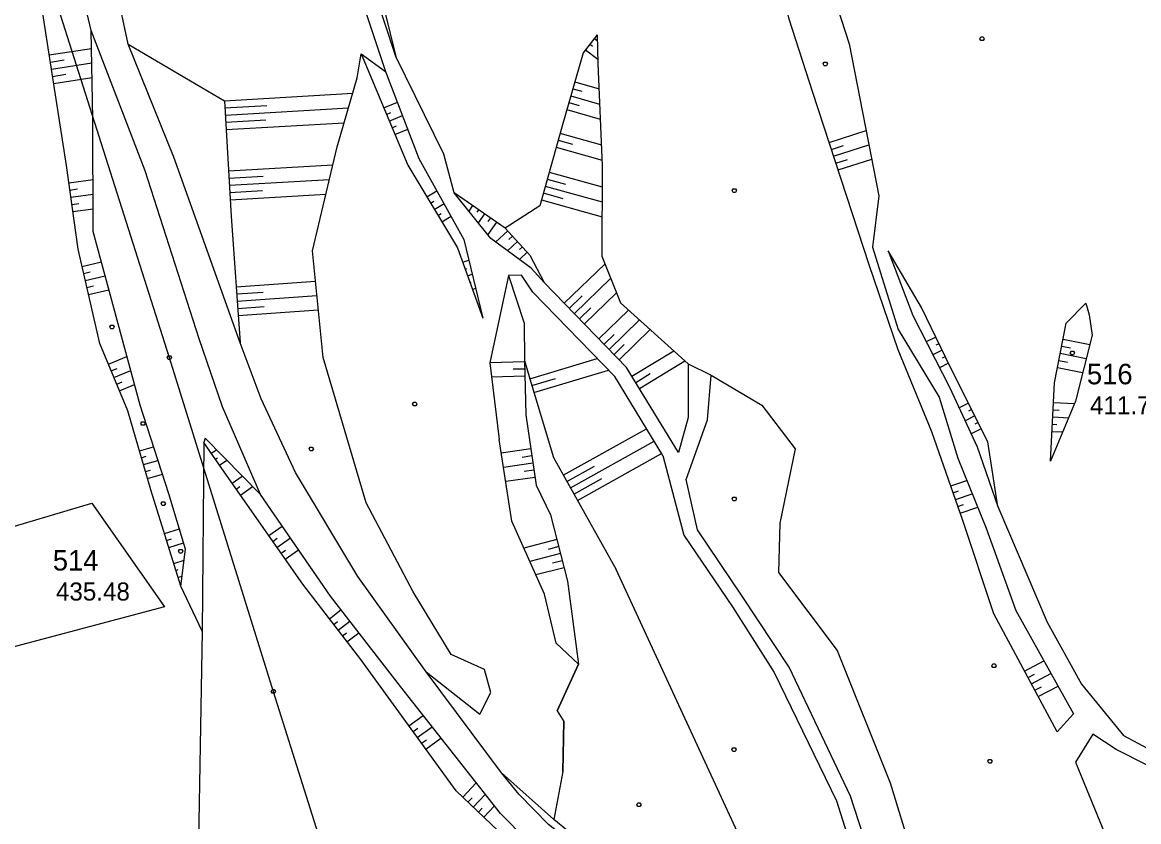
# Model space of a CAD drawing. Extents: x -664960 to -662754, y -993849 to -991145.
# Drawn here: x -663833.4 to -663648.1, y -993552.6 to -993419.9 of the extents above; entities that cross this region are included whole.
import ezdxf

# ---------------------------------------------------------------- set-up
doc = ezdxf.new("R2010")
doc.units = 0
for name, color, linetype in [('Vrstva 1', 7, 'Continuous'), ('Vrstva 13', 7, 'Continuous'), ('Vrstva 23', 7, 'Continuous'), ('Vrstva 27', 7, 'Continuous'), ('Vrstva 37', 7, 'Continuous'), ('Vrstva 57', 7, 'Continuous'), ('Vrstva 63', 7, 'Continuous'), ('Vrstva 8', 7, 'Continuous')]:
    doc.layers.add(name, color=color, linetype=linetype)

msp = doc.modelspace()

# ---------------------------------------------------------------- linework, layer by layer
at = {"layer": 'Vrstva 13'}
for points in [[(-663673.965, -993422.37), (-663673.786, -993422.67), (-663673.965, -993422.97), (-663674.326, -993422.97), (-663674.506, -993422.67), (-663674.326, -993422.37), (-663673.965, -993422.37)], [(-663699.967, -993426.545), (-663699.787, -993426.845), (-663699.967, -993427.145), (-663700.327, -993427.145), (-663700.507, -993426.845), (-663700.327, -993426.545), (-663699.967, -993426.545)], [(-663715.06, -993447.588), (-663714.88, -993447.888), (-663715.06, -993448.188), (-663715.42, -993448.188), (-663715.6, -993447.888), (-663715.42, -993447.588), (-663715.06, -993447.588)], [(-663768.107, -993483.011), (-663767.927, -993483.311), (-663768.107, -993483.611), (-663768.467, -993483.611), (-663768.647, -993483.311), (-663768.467, -993483.011), (-663768.107, -993483.011)], [(-663785.301, -993490.467), (-663785.121, -993490.767), (-663785.301, -993491.067), (-663785.661, -993491.067), (-663785.841, -993490.767), (-663785.661, -993490.467), (-663785.301, -993490.467)], [(-663715.062, -993498.751), (-663714.883, -993499.051), (-663715.062, -993499.351), (-663715.423, -993499.351), (-663715.602, -993499.051), (-663715.423, -993498.751), (-663715.062, -993498.751)], [(-663715.121, -993540.383), (-663714.941, -993540.683), (-663715.121, -993540.983), (-663715.481, -993540.983), (-663715.661, -993540.683), (-663715.481, -993540.383), (-663715.121, -993540.383)], [(-663730.907, -993549.527), (-663730.727, -993549.827), (-663730.907, -993550.127), (-663731.267, -993550.127), (-663731.447, -993549.827), (-663731.267, -993549.527), (-663730.907, -993549.527)]]:
    msp.add_lwpolyline(points, dxfattribs=at)
at = {"layer": 'Vrstva 23'}
for points in [[(-663661.79, -993680.84), (-663666.37, -993671.83), (-663676.16, -993653.43), (-663682.14, -993639.66), (-663688.35, -993624.08), (-663695.39, -993604.45), (-663700.87, -993593.48), (-663716.11, -993576), (-663718.69, -993573.73), (-663734.89, -993562.06), (-663746.09, -993553.11), (-663750.94, -993548.15), (-663753.89, -993544.52), (-663766.4, -993527.77), (-663777.73, -993511.96), (-663788.08, -993494.69), (-663793.77, -993482.43), (-663797.29, -993473.16), (-663808.27, -993442.31), (-663815.88, -993423.57), (-663819.75, -993405.36)], [(-663667.19, -993679.26), (-663670.59, -993672.44), (-663678.35, -993658.11), (-663686.67, -993641.66), (-663696.49, -993616.58), (-663704.03, -993599.55), (-663711.55, -993587), (-663718.59, -993580.09), (-663723.96, -993575.78), (-663738.28, -993566.28), (-663745.54, -993559.93), (-663754.09, -993551.29), (-663770.68, -993530.21), (-663782.31, -993515.19), (-663793.9, -993498.34), (-663800.21, -993483.78), (-663804.11, -993472.49), (-663813.07, -993444.61), (-663822.04, -993421.3), (-663825.37, -993406.88)]]:
    msp.add_lwpolyline(points, dxfattribs=at)
at = {"layer": 'Vrstva 27'}
for points in [[(-663801.76, -993299.65), (-663795.03, -993309.25), (-663792.38, -993316.79), (-663793.14, -993330.32), (-663794.38, -993341), (-663793.4, -993359.71), (-663792.35, -993365.73), (-663782.84, -993399.06), (-663777.61, -993414.6), (-663773.14, -993428.09), (-663767.61, -993442.53), (-663760.13, -993455.98), (-663757.01, -993469.03)], [(-663761.74, -993448.27), (-663763.46, -993441.81), (-663771.43, -993425.6), (-663775.14, -993414.33), (-663780.54, -993398.22), (-663789.72, -993365.14), (-663789.63, -993361.27), (-663786.59, -993346.37), (-663786.78, -993340.33), (-663786.12, -993339.31)], [(-663724.53, -993491.38), (-663733.123, -993477.249), (-663746.81, -993463.12), (-663748.95, -993460.77), (-663755.69, -993455.81), (-663761.74, -993448.27)], [(-663692.33, -993457.26), (-663688.06, -993470.93), (-663681.24, -993482.18), (-663678.17, -993492.32), (-663673.42, -993503.9), (-663668.52, -993517.59), (-663658.93, -993534.73)], [(-663689.72, -993457.9), (-663685.64, -993468.6), (-663679.48, -993480.64), (-663674.92, -993490.39), (-663671.48, -993500.33), (-663663.31, -993519.51), (-663657.6, -993529.8), (-663650.64, -993538.31), (-663640.39, -993543.81), (-663631.04, -993549.21), (-663624.53, -993556.43), (-663617.48, -993569.92), (-663602.27, -993592.27), (-663588.6, -993606.58), (-663587.98, -993607.73)], [(-663727.12, -993491.86), (-663735.08, -993478.74), (-663748.71, -993464.74), (-663750.56, -993461.93), (-663752.75, -993461.99)], [(-663722.91, -993476.61), (-663722.92, -993485.53), (-663724.53, -993491.38)], [(-663617.75, -993688.33), (-663621.2, -993684.71), (-663623.27, -993672.48), (-663626.03, -993651.59), (-663631.7, -993630.02), (-663637.5, -993620.58), (-663645.57, -993611.43), (-663656.3, -993604.85), (-663664.96, -993599.76), (-663673.95, -993591.13), (-663682.59, -993580.63), (-663689.69, -993567.67), (-663695.94, -993548.39), (-663706.15, -993526.98), (-663713.97, -993515.23), (-663721.34, -993504.19), (-663723.25, -993495.81), (-663719.71, -993485.94), (-663719.1, -993478.49)], [(-663727.12, -993491.86), (-663723.61, -993505.05), (-663715.54, -993517), (-663708.61, -993527.89), (-663698.31, -993549.18), (-663692.46, -993567.57), (-663684.5, -993582.39), (-663676.76, -993593.09), (-663666.63, -993601.82), (-663657.5, -993607.21), (-663648.73, -993613.27), (-663639.9, -993622.05), (-663634.08, -993630.75), (-663628.07, -993651.96), (-663625.42, -993672.38), (-663625.87, -993685.44), (-663628.47, -993695.31), (-663629.86, -993703.76)]]:
    msp.add_lwpolyline(points, dxfattribs=at)
at = {"layer": 'Vrstva 37'}
for points in [[(-663808.86, -993475.3), (-663808.68, -993475.6), (-663808.86, -993475.9), (-663809.22, -993475.9), (-663809.4, -993475.6), (-663809.22, -993475.3), (-663808.86, -993475.3)], [(-663791.61, -993530.72), (-663791.43, -993531.02), (-663791.61, -993531.32), (-663791.97, -993531.32), (-663792.15, -993531.02), (-663791.97, -993530.72), (-663791.61, -993530.72)]]:
    msp.add_lwpolyline(points, dxfattribs=at)
at = {"layer": 'Vrstva 57'}
msp.add_lwpolyline([(-663937.17, -993067.28), (-663921.25, -993118.58), (-663905.79, -993167.82), (-663887.66, -993226.85), (-663873.48, -993270.98), (-663861.55, -993308.04), (-663843.55, -993366.56), (-663828.28, -993415.08), (-663809.04, -993475.6), (-663791.79, -993531.02), (-663772.5, -993592.28), (-663754.33, -993650.13), (-663735.8, -993708.15), (-663717.65, -993766.39)], dxfattribs=at)
at = {"layer": 'Vrstva 63'}
for p, q in [((-663828.97, -993425.353), (-663821.977, -993424.269)), ((-663739.203, -993423.568), (-663738.786, -993423.891)), ((-663738.469, -993422.619), (-663737.994, -993422.987)), ((-663777.19, -993425.18), (-663773.14, -993428.09)), ((-663739.938, -993424.517), (-663737.909, -993426.088)), ((-663828.786, -993426.539), (-663826.51, -993426.186)), ((-663828.602, -993427.725), (-663821.926, -993426.689)), ((-663828.418, -993428.911), (-663826.248, -993428.574)), ((-663828.235, -993430.097), (-663821.874, -993429.11)), ((-663741.718, -993429.821), (-663737.711, -993430.985)), ((-663799.88, -993432.95), (-663778.597, -993431.717)), ((-663742.053, -993430.973), (-663740.589, -993431.398)), ((-663773.446, -993434.125), (-663771.19, -993433.181)), ((-663742.722, -993433.278), (-663741, -993433.778)), ((-663742.388, -993432.125), (-663737.603, -993433.516)), ((-663799.811, -993434.148), (-663792.864, -993433.746)), ((-663799.741, -993435.346), (-663779.302, -993434.162)), ((-663772.983, -993435.232), (-663772.243, -993434.922)), ((-663772.52, -993436.339), (-663770.332, -993435.423)), ((-663743.057, -993434.43), (-663737.495, -993436.046)), ((-663799.672, -993436.544), (-663793.006, -993436.158)), ((-663799.602, -993437.742), (-663780.007, -993436.607)), ((-663772.056, -993437.446), (-663771.339, -993437.146)), ((-663771.593, -993438.553), (-663769.473, -993437.666)), ((-663744.189, -993438.365), (-663737.315, -993440.287)), ((-663699.502, -993439.894), (-663693.362, -993437.894)), ((-663744.836, -993440.676), (-663737.207, -993442.809)), ((-663744.513, -993439.52), (-663742.098, -993440.196)), ((-663699.13, -993441.035), (-663697.132, -993440.385)), ((-663698.758, -993442.176), (-663692.901, -993440.268)), ((-663698.386, -993443.317), (-663696.483, -993442.697)), ((-663698.015, -993444.458), (-663692.44, -993442.642)), ((-663799.205, -993444.604), (-663781.877, -993443.6)), ((-663825.723, -993446.601), (-663821.698, -993446.044)), ((-663799.135, -993445.802), (-663793.486, -993445.474)), ((-663799.066, -993447), (-663782.46, -993446.037)), ((-663746.315, -993445.966), (-663743.275, -993446.816)), ((-663745.992, -993444.81), (-663737.182, -993447.274)), ((-663825.558, -993447.789), (-663824.272, -993447.611)), ((-663798.997, -993448.198), (-663793.587, -993447.884)), ((-663766.292, -993448.935), (-663764.609, -993447.926)), ((-663753.3, -993454.09), (-663761.74, -993448.27)), ((-663746.962, -993448.277), (-663743.709, -993449.187)), ((-663746.639, -993447.121), (-663737.19, -993449.764)), ((-663825.394, -993448.978), (-663821.69, -993448.465)), ((-663825.23, -993450.167), (-663824.05, -993450.003)), ((-663798.927, -993449.396), (-663783.042, -993448.475)), ((-663765.675, -993449.964), (-663765.126, -993449.635)), ((-663765.058, -993450.993), (-663763.442, -993450.025)), ((-663747.285, -993449.433), (-663737.198, -993452.254)), ((-663825.065, -993451.355), (-663821.682, -993450.887)), ((-663764.441, -993452.023), (-663763.914, -993451.707)), ((-663758.692, -993450.372), (-663759.321, -993451.285)), ((-663757.704, -993451.053), (-663757.981, -993451.456)), ((-663756.716, -993451.735), (-663757.753, -993453.239)), ((-663763.824, -993453.052), (-663762.275, -993452.123)), ((-663754.74, -993453.097), (-663756.185, -993455.193)), ((-663755.728, -993452.416), (-663756.141, -993453.015)), ((-663752.862, -993454.567), (-663754.872, -993456.412)), ((-663752.051, -993455.451), (-663752.662, -993456.012)), ((-663751.239, -993456.335), (-663752.902, -993457.861)), ((-663750.428, -993457.219), (-663750.924, -993457.674)), ((-663760.36, -993459.782), (-663759.312, -993459.402)), ((-663749.617, -993458.103), (-663750.932, -993459.311)), ((-663823.544, -993460.457), (-663820.315, -993459.713)), ((-663823.275, -993461.627), (-663822.185, -993461.376)), ((-663759.951, -993460.91), (-663759.645, -993460.799)), ((-663743.474, -993466.564), (-663736.716, -993460.017)), ((-663823.006, -993462.796), (-663819.692, -993462.033)), ((-663797.946, -993463.836), (-663784.787, -993462.911)), ((-663759.543, -993462.038), (-663758.75, -993461.751)), ((-663759.134, -993463.166), (-663758.913, -993463.086)), ((-663741.804, -993468.287), (-663735.762, -993462.434)), ((-663822.736, -993463.965), (-663821.619, -993463.708)), ((-663822.467, -993465.135), (-663819.068, -993464.352)), ((-663797.861, -993465.033), (-663793.468, -993464.724)), ((-663758.725, -993464.295), (-663758.189, -993464.1)), ((-663740.134, -993470.011), (-663734.808, -993464.852)), ((-663797.777, -993466.23), (-663784.548, -993465.3)), ((-663742.639, -993467.426), (-663740.508, -993465.361)), ((-663797.693, -993467.427), (-663793.276, -993467.117)), ((-663797.609, -993468.624), (-663784.309, -993467.689)), ((-663740.969, -993469.149), (-663739.076, -993467.316)), ((-663737.715, -993472.509), (-663732.792, -993467.739)), ((-663736.045, -993474.232), (-663731.001, -993469.347)), ((-663736.88, -993473.371), (-663735.22, -993471.763)), ((-663734.375, -993475.956), (-663729.211, -993470.954)), ((-663681.789, -993472.23), (-663683.387, -993473.004)), ((-663735.21, -993475.094), (-663733.51, -993473.448)), ((-663681.266, -993473.31), (-663681.79, -993473.564)), ((-663660.897, -993473.713), (-663659.446, -993474)), ((-663660.665, -993472.536), (-663656.243, -993473.41)), ((-663819.155, -993476.692), (-663816.091, -993475.409)), ((-663749.22, -993479.11), (-663738.003, -993475.737)), ((-663732.248, -993478.688), (-663725.301, -993474.463)), ((-663731.001, -993480.738), (-663723.436, -993476.138)), ((-663680.743, -993474.39), (-663682.294, -993475.141)), ((-663680.22, -993475.47), (-663680.728, -993475.716)), ((-663661.363, -993476.068), (-663659.953, -993476.346)), ((-663661.13, -993474.891), (-663656.835, -993475.739)), ((-663818.691, -993477.799), (-663817.72, -993477.392)), ((-663818.228, -993478.905), (-663815.458, -993477.746)), ((-663750.084, -993476.297), (-663755.85, -993476.45)), ((-663750.052, -993477.496), (-663751.934, -993477.546)), ((-663748.529, -993481.408), (-663736.116, -993477.676)), ((-663679.697, -993476.55), (-663681.2, -993477.278)), ((-663661.595, -993477.245), (-663657.426, -993478.069)), ((-663817.764, -993480.012), (-663816.891, -993479.647)), ((-663750.02, -993478.696), (-663755.556, -993478.843)), ((-663748.874, -993480.259), (-663744.94, -993479.076)), ((-663731.625, -993479.713), (-663729.208, -993478.244)), ((-663817.301, -993481.119), (-663814.825, -993480.083)), ((-663676.399, -993483.147), (-663677.945, -993483.923)), ((-663662.26, -993483.062), (-663658.803, -993483.232)), ((-663675.323, -993485.292), (-663676.927, -993486.098)), ((-663675.861, -993484.22), (-663676.385, -993484.483)), ((-663662.378, -993485.459), (-663659.77, -993485.587)), ((-663662.319, -993484.261), (-663661.309, -993484.31)), ((-663674.784, -993486.365), (-663675.329, -993486.638)), ((-663662.437, -993486.658), (-663661.71, -993486.694)), ((-663743.64, -993495.134), (-663729.818, -993487.413)), ((-663674.246, -993487.437), (-663675.91, -993488.273)), ((-663662.496, -993487.856), (-663660.737, -993487.943)), ((-663813.985, -993491.064), (-663811.67, -993490.392)), ((-663802.074, -993491.486), (-663801.223, -993490.897)), ((-663749.032, -993490.732), (-663753.937, -993491.445)), ((-663742.47, -993497.229), (-663728.572, -993489.467)), ((-663813.65, -993492.217), (-663812.868, -993491.989)), ((-663813.315, -993493.369), (-663810.931, -993492.676)), ((-663801.391, -993492.473), (-663801.051, -993492.237)), ((-663800.708, -993493.459), (-663799.515, -993492.633)), ((-663748.859, -993491.92), (-663750.489, -993492.157)), ((-663741.3, -993499.324), (-663727.326, -993491.52)), ((-663812.98, -993494.521), (-663812.175, -993494.287)), ((-663748.687, -993493.108), (-663753.57, -993493.817)), ((-663748.514, -993494.295), (-663750.137, -993494.531)), ((-663743.055, -993496.181), (-663738.44, -993493.603)), ((-663812.645, -993495.674), (-663810.191, -993494.961)), ((-663798.619, -993496.453), (-663796.924, -993495.267)), ((-663748.341, -993495.483), (-663753.204, -993496.189)), ((-663741.885, -993498.277), (-663737.244, -993495.685)), ((-663679.331, -993496.903), (-663676.67, -993495.976)), ((-663797.931, -993497.436), (-663797.311, -993497.003)), ((-663797.243, -993498.419), (-663795.217, -993497.002)), ((-663678.937, -993498.036), (-663678.03, -993497.72)), ((-663678.542, -993499.169), (-663675.758, -993498.2)), ((-663678.147, -993500.303), (-663677.2, -993499.973)), ((-663677.752, -993501.436), (-663674.846, -993500.423)), ((-663792.549, -993505.133), (-663790.306, -993503.564)), ((-663809.851, -993504.811), (-663807.373, -993504.043)), ((-663809.495, -993505.957), (-663808.673, -993505.702)), ((-663791.861, -993506.116), (-663791.117, -993505.596)), ((-663791.173, -993507.099), (-663788.946, -993505.542)), ((-663744.693, -993505.823), (-663750.188, -993507.225)), ((-663809.14, -993507.103), (-663806.677, -993506.34)), ((-663790.486, -993508.083), (-663789.747, -993507.566)), ((-663789.798, -993509.066), (-663787.586, -993507.519)), ((-663744.396, -993506.985), (-663746.159, -993507.435)), ((-663808.31, -993509.782), (-663806.585, -993509.247)), ((-663744.099, -993508.148), (-663749.191, -993509.448)), ((-663743.803, -993509.311), (-663745.431, -993509.727)), ((-663807.955, -993510.928), (-663807.555, -993510.804)), ((-663743.506, -993510.474), (-663748.195, -993511.67)), ((-663807.6, -993512.074), (-663806.922, -993511.864)), ((-663782.478, -993518.96), (-663780.543, -993517.472)), ((-663781.746, -993519.911), (-663781.101, -993519.415)), ((-663781.014, -993520.862), (-663779.074, -993519.369)), ((-663780.283, -993521.813), (-663779.636, -993521.315)), ((-663779.551, -993522.764), (-663777.605, -993521.267)), ((-663667.053, -993527.641), (-663663.855, -993525.927)), ((-663665.919, -993529.757), (-663662.683, -993528.022)), ((-663666.486, -993528.699), (-663665.415, -993528.125)), ((-663665.352, -993530.814), (-663664.268, -993530.233)), ((-663664.785, -993531.872), (-663661.511, -993530.117)), ((-663769.287, -993536.721), (-663766.913, -993534.997)), ((-663768.582, -993537.692), (-663767.779, -993537.108)), ((-663767.876, -993538.663), (-663765.428, -993536.884)), ((-663767.171, -993539.633), (-663766.343, -993539.032)), ((-663766.466, -993540.604), (-663763.942, -993538.771)), ((-663760.332, -993548.576), (-663758.083, -993546.216)), ((-663758.595, -993550.231), (-663756.584, -993548.121)), ((-663759.463, -993549.403), (-663758.754, -993548.659)), ((-663756.857, -993551.887), (-663755.084, -993550.027)), ((-663757.726, -993551.059), (-663757.096, -993550.398))]:
    msp.add_line(p, q, dxfattribs=at)
for points in [[(-663658.93, -993534.73), (-663661.64, -993537.74), (-663672.14, -993518.15), (-663677.34, -993502.62), (-663682.45, -993487.95), (-663688.07, -993474.33), (-663692.88, -993460.22), (-663702.21, -993431.58), (-663706.13, -993419.4), (-663711.81, -993395.54), (-663712.97, -993379.02), (-663715.63, -993364.73), (-663721.84, -993352.77), (-663727.79, -993326.42), (-663739.71, -993310.26), (-663749.83, -993296.15)], [(-663726.89, -993308.98), (-663728.8, -993313.46), (-663724.93, -993322.53), (-663722.15, -993326.98), (-663718.55, -993347.61), (-663717.05, -993355.95), (-663709.92, -993369.45), (-663704.49, -993390.15), (-663702.74, -993403.3), (-663696.16, -993423.49), (-663691.25, -993448.77), (-663692.33, -993457.26)], [(-663803.57, -993521.02), (-663807.14, -993513.56), (-663812.1, -993497.55), (-663815.91, -993484.44), (-663820.6, -993473.24), (-663824.2, -993457.61), (-663826.12, -993443.73), (-663830.59, -993414.91), (-663841.03, -993379.83), (-663850.21, -993353.11), (-663857.31, -993330.23), (-663860.52, -993318.79), (-663859.27, -993318.31)], [(-663786.59, -993346.37), (-663786.79, -993361.37), (-663786.23, -993369.49), (-663783.47, -993376.36), (-663779.33, -993398.01), (-663774.19, -993414.34), (-663771.43, -993425.6)], [(-663807.14, -993513.56), (-663806.35, -993507.42), (-663809.14, -993498.21), (-663813.9, -993483.5), (-663817, -993472.05), (-663821.67, -993454.67), (-663821.73, -993435.9), (-663822.04, -993421.3)], [(-663738.02, -993422.04), (-663740.32, -993425.01), (-663743.9, -993437.33), (-663747.55, -993450.38), (-663753.3, -993454.09), (-663749.17, -993458.59), (-663746.81, -993463.12)], [(-663738.02, -993422.04), (-663737.89, -993426.77), (-663737.17, -993443.69), (-663737.22, -993458.74), (-663734.15, -993466.52), (-663722.91, -993476.61), (-663719.1, -993478.49), (-663710.66, -993483.47), (-663705.13, -993490.75), (-663707.72, -993503.11), (-663707.9, -993511.3), (-663698.18, -993524.21), (-663689.36, -993546.2), (-663685.91, -993557.61), (-663685.56, -993568.29), (-663682.8, -993576.7), (-663677.88, -993585.26), (-663673.95, -993591.13)], [(-663815.88, -993423.57), (-663799.88, -993432.95), (-663798.77, -993452.11), (-663797.29, -993473.16)], [(-663766.4, -993527.77), (-663757.52, -993534.78), (-663755.67, -993531.2), (-663756.74, -993527.36), (-663762.26, -993524.88), (-663768.57, -993514.49), (-663776.39, -993499.69), (-663783.52, -993475.57), (-663785.29, -993457.88), (-663781.17, -993440.64), (-663777.86, -993429.16), (-663777.19, -993425.18)], [(-663777.19, -993425.18), (-663769.46, -993443.65), (-663761.23, -993457.38), (-663757.01, -993469.03)], [(-663671.48, -993500.33), (-663673.17, -993489.58), (-663679.3, -993477.37), (-663684.19, -993467.27), (-663689.72, -993457.9)], [(-663752.75, -993461.99), (-663755.85, -993476.45), (-663754.28, -993489.22)], [(-663752.75, -993461.99), (-663750.15, -993469.89), (-663750.09, -993476.07), (-663749.85, -993485.1), (-663748.15, -993496.8), (-663745.74, -993501.72), (-663742.93, -993512.73), (-663741.09, -993526.47)], [(-663662.74, -993492.82), (-663662.1, -993479.8), (-663660.14, -993469.88), (-663656.87, -993466.59), (-663656.32, -993468.48), (-663655.85, -993471.86), (-663658.63, -993482.81), (-663662.74, -993492.82)], [(-663818.37, -993470.21), (-663818.19, -993470.51), (-663818.37, -993470.81), (-663818.73, -993470.81), (-663818.91, -993470.51), (-663818.73, -993470.21), (-663818.37, -993470.21)], [(-663750.09, -993476.07), (-663749.22, -993479.11), (-663745.29, -993492.18), (-663734.89, -993510.8)], [(-663813.22, -993486.24), (-663813.04, -993486.54), (-663813.22, -993486.84), (-663813.58, -993486.84), (-663813.76, -993486.54), (-663813.58, -993486.24), (-663813.22, -993486.24)], [(-663793.9, -993498.34), (-663803.1, -993488.99), (-663803.31, -993489.7)], [(-663738.28, -993566.28), (-663749.75, -993558.66), (-663761.45, -993547.51), (-663777.27, -993525.73), (-663786.9, -993513.21), (-663800.32, -993494.02), (-663803.31, -993489.7), (-663803.57, -993521.02), (-663804.29, -993562.17)], [(-663741.09, -993526.47), (-663744.82, -993522.98), (-663746.76, -993514.87), (-663752.19, -993502.76), (-663754.28, -993489.22)], [(-663930.3, -993537.48), (-663930.01, -993521.07), (-663903.63, -993519.04), (-663885.76, -993516.45), (-663856.69, -993509.96), (-663839.47, -993504.99), (-663821.9, -993499.76), (-663809.83, -993516.96), (-663846.77, -993526.75), (-663876.87, -993533.14), (-663901.79, -993535.56), (-663930.3, -993537.48)], [(-663809.87, -993499.54), (-663809.69, -993499.84), (-663809.87, -993500.14), (-663810.23, -993500.14), (-663810.41, -993499.84), (-663810.23, -993499.54), (-663809.87, -993499.54)], [(-663676.16, -993653.43), (-663677.09, -993640.66), (-663681.85, -993621.36), (-663692.16, -993602.58), (-663699.95, -993587.12), (-663707.33, -993570.44), (-663734.89, -993510.8)], [(-663744.63, -993534.25), (-663741.09, -993526.47), (-663744.63, -993534.25), (-663743.54, -993536.02), (-663743.73, -993544.3), (-663743.54, -993536.02), (-663743.73, -993544.3), (-663745.21, -993552.26)], [(-663671.96, -993526.45), (-663671.78, -993526.75), (-663671.96, -993527.05), (-663672.32, -993527.05), (-663672.5, -993526.75), (-663672.32, -993526.45), (-663671.96, -993526.45)], [(-663637.5, -993620.58), (-663632.8, -993623.03), (-663625.63, -993635.33), (-663621.11, -993640.02), (-663617.42, -993636.17), (-663616.91, -993631.39), (-663618.98, -993620.32), (-663620.53, -993607.84), (-663620.85, -993601.25), (-663618.25, -993592.11), (-663618.68, -993575.3), (-663626.87, -993557.84), (-663632.85, -993551.75), (-663641.54, -993545.88), (-663651.88, -993540.66), (-663655.74, -993538.09), (-663658.63, -993542.75), (-663649.14, -993565.86), (-663647.09, -993581.45), (-663644.28, -993593.08), (-663645.57, -993607.08), (-663645.57, -993611.43)], [(-663672.65, -993542.32), (-663672.47, -993542.62), (-663672.65, -993542.92), (-663673.01, -993542.92), (-663673.19, -993542.62), (-663673.01, -993542.32), (-663672.65, -993542.32)], [(-663716.11, -993576), (-663705.98, -993585.35), (-663698.04, -993596.15), (-663706.44, -993581.75), (-663712.48, -993576.46), (-663734.42, -993561.14), (-663745.21, -993552.26), (-663753.89, -993544.52)]]:
    msp.add_lwpolyline(points, dxfattribs=at)
at = {"layer": 'Vrstva 8'}
for points in [[(-663658.94, -993474.53), (-663658.76, -993474.83), (-663658.94, -993475.13), (-663659.3, -993475.13), (-663659.48, -993474.83), (-663659.3, -993474.53), (-663658.94, -993474.53)], [(-663806.99, -993507.44), (-663806.81, -993507.74), (-663806.99, -993508.04), (-663807.35, -993508.04), (-663807.53, -993507.74), (-663807.35, -993507.44), (-663806.99, -993507.44)]]:
    msp.add_lwpolyline(points, dxfattribs=at)

# ---------------------------------------------------------------- texts
at = {"layer": 'Vrstva 1'}
for s, p in [('516', (-663656.72, -993480.03)), ('514', (-663828.384, -993510.949))]:
    msp.add_text(s, height=3.4, dxfattribs=at).set_placement(p)
at = {"layer": 'Vrstva 63'}
for s, p in [('411.76', (-663656.196, -993485.01)), ('435.48', (-663827.86, -993515.929))]:
    msp.add_text(s, height=3, dxfattribs=at).set_placement(p)

doc.saveas('drawing.dxf')
